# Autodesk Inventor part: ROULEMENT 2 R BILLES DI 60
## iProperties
Created: 2004-11
Part Number: ROULEMENT 2 R BILLES DI 60
Document SubType Name: Modeling
Designer: Bruno
Manufacturer: Standard
Standards Organization: Custom
Author: Bruno
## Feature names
1. Base1
